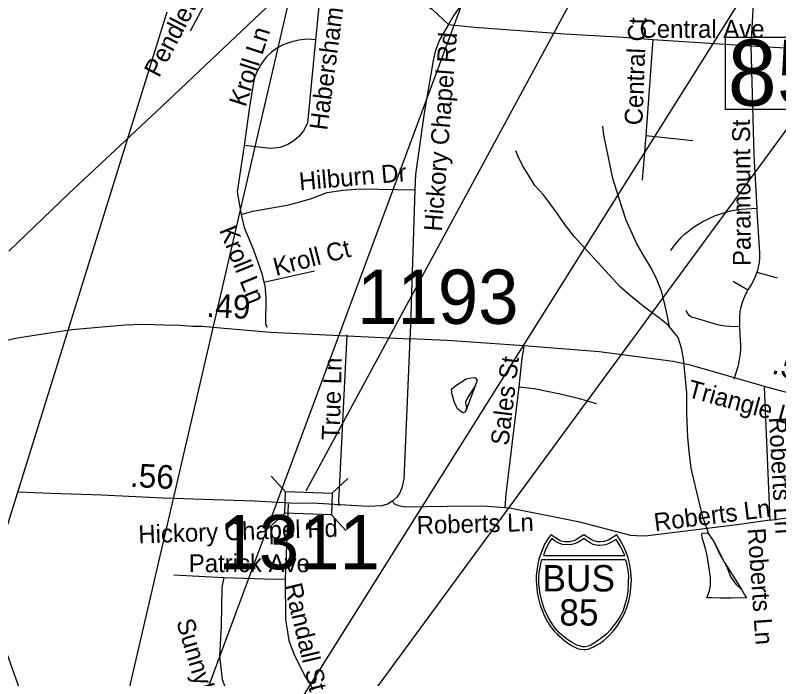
# Model space of a CAD drawing. Extents: x 1662474 to 1856135, y 779280 to 917889.
# Drawn here: x 1711717 to 1715769, y 802097 to 805619 of the extents above; entities that cross this region are included whole.
import ezdxf

# ---------------------------------------------------------------- set-up
doc = ezdxf.new("R2010")
doc.units = 0
for name, color, linetype in [('Cogo Default Point CELL', 7, 'Continuous'), ('Exist Hydrographic Misc Water Feature', 7, 'Continuous'), ('Exist Road Non-System Type 51', 7, 'Continuous'), ('Exist Road Non-System Type 51 Label', 7, 'Continuous'), ('Exist Road Primary Interstate Shield Number Label', 7, 'Continuous'), ('Exist Road Primary Interstate Structure Ovrhead Sign CELL', 7, 'Continuous'), ('Exist Road Primary US Ramp 1 Lane  Attributed', 7, 'Continuous'), ('Exist Road Secondary Mileage Tenths English Label', 7, 'Continuous'), ('Exist Road Secondary Structure Standard Bridge CELL', 7, 'Continuous'), ('Exist Road Secondary Structure Standard Bridge Number Label', 7, 'Continuous'), ('Exist Road Secondary Type 51 Attributed', 7, 'Continuous'), ('Exist Road Secondary Type 51 Label', 7, 'Continuous'), ('Exist Road Secondary Type 51 Undivided 4 Lane Attributed', 7, 'Continuous'), ('Exist Utilities Electrical Transmission Line', 7, 'Continuous'), ('Prop DGN Element Guardrail', 7, 'Continuous'), ('Prop Roadway Culvert', 7, 'Continuous'), ('Scratch_Level_2', 7, 'Continuous')]:
    doc.layers.add(name, color=color, linetype=linetype)

msp = doc.modelspace()

# ---------------------------------------------------------------- linework, layer by layer
at = {"layer": 'Exist Hydrographic Misc Water Feature'}
for points in [[(1715189.8, 803964.3), (1715176.4, 804028.4), (1715161.1, 804098.6), (1715147.6, 804154.8), (1715120.2, 804221), (1715090.7, 804279.3), (1715053.4, 804341.7), (1715015.9, 804406.1), (1714959.1, 804530.7), (1714918.2, 804657.1), (1714889.2, 804751.4), (1714852.8, 804923.8), (1714841.3, 804981.9), (1714835.7, 805030)], [(1715189.8, 803964.3), (1715181.8, 803974.4), (1715130.3, 804016.9), (1715058.7, 804067.6), (1714993.2, 804120.2), (1714929.7, 804174.8), (1714791.1, 804326.2), (1714684.2, 804445.2), (1714634.9, 804507.7), (1714591.4, 804570.1), (1714520.2, 804664.9), (1714474.7, 804715.3), (1714453, 804749.6), (1714409.7, 804822), (1714384.1, 804872.2), (1714374.3, 804898.4)], [(1715399.5, 802860), (1715366.4, 802954.3), (1715318.2, 803154.9), (1715304.8, 803215), (1715293.6, 803303.1), (1715286.2, 803377.2), (1715281.5, 803503.3), (1715282.5, 803615.3), (1715264.3, 803797.6), (1715252.7, 803851.7), (1715235.3, 803907.9), (1715189.8, 803964.3)], [(1714032.3, 803633.2), (1714056.4, 803652.9), (1714110.8, 803688.5), (1714137, 803694.2), (1714157, 803696), (1714168.9, 803681.9), (1714158.6, 803652), (1714134.2, 803612.2), (1714120, 803592.3), (1714107.7, 803564.5), (1714111.5, 803532.4), (1714107.2, 803514.4), (1714093.2, 803508.6), (1714065.3, 803528.8), (1714047.7, 803563), (1714036.1, 803605.1), (1714032.3, 803633.2)], [(1714032.3, 803633.2), (1714056.4, 803652.9), (1714110.8, 803688.5), (1714137, 803694.2), (1714157, 803696), (1714168.9, 803681.9), (1714158.6, 803652), (1714107.2, 803514.4), (1714093.2, 803508.6), (1714065.3, 803528.8), (1714047.7, 803563), (1714036.1, 803605.1), (1714032.3, 803633.2)], [(1715514.2, 802524.8), (1715460.2, 802525.3), (1715412.2, 802525.8), (1715388.2, 802526), (1715402.6, 802563.9), (1715406.9, 802593.8), (1715407.4, 802635.8), (1715399.7, 802681.9), (1715394, 802714), (1715390.4, 802752), (1715380.7, 802788.2), (1715371, 802816.2), (1715363.2, 802844.4), (1715361.5, 802862.4), (1715365.5, 802872.3), (1715391.5, 802870.1), (1715399.5, 802860)], [(1715514.2, 802524.8), (1715460.2, 802525.3), (1715412.2, 802525.8), (1715388.2, 802526), (1715402.6, 802563.9), (1715406.9, 802593.8), (1715407.4, 802635.8), (1715390.4, 802752), (1715380.7, 802788.2), (1715371, 802816.2), (1715363.2, 802844.4), (1715361.5, 802862.4), (1715365.5, 802872.3), (1715391.5, 802870.1), (1715399.5, 802860)], [(1715399.5, 802860), (1715425.1, 802825.8), (1715454.5, 802759.4), (1715482.1, 802713.2), (1715495.9, 802685), (1715515.4, 802636.8), (1715541, 802598.6), (1715572.8, 802568.3), (1715586.5, 802546.1), (1715598.4, 802526), (1715518.2, 802524.8), (1715514.2, 802524.8)], [(1715399.5, 802860), (1715425.1, 802825.8), (1715482.1, 802713.2), (1715572.8, 802568.3), (1715586.5, 802546.1), (1715598.4, 802526), (1715518.2, 802524.8), (1715514.2, 802524.8)]]:
    msp.add_lwpolyline(points, dxfattribs=at)
at = {"layer": 'Exist Road Non-System Type 51'}
for p, q in [((1715641.1, 805800.6), (1715620.9, 805456.9)), ((1715102, 805490.7), (1715063.4, 804979.7)), ((1715102, 805490.7), (1715620.9, 805456.9)), ((1715620.9, 805456.9), (1716237.8, 805419)), ((1715063.4, 804979.7), (1715045.4, 804743.2)), ((1715063.4, 804979.7), (1715313.4, 804953.4)), ((1713037.2, 804202.2), (1713305.5, 804262.4)), ((1715653.5, 804255.2), (1715761.1, 804224.2)), ((1715528.2, 804206.9), (1715606, 804160.5)), ((1715692.4, 803644.5), (1715723, 802939.2)), ((1713166.1, 803025.1), (1713150.6, 802627.8)), ((1715723, 802939.2), (1715937.8, 802967.9)), ((1712558.8, 802649), (1712824.1, 802634.9))]:
    msp.add_line(p, q, dxfattribs=at)
for points in [[(1713199.4, 806012.9), (1713249.9, 805952.6), (1713287.6, 805887.8), (1713319.4, 805794.9), (1713328.9, 805664.2), (1713311.2, 805488.6)], [(1712742.2, 805934.8), (1712726.8, 805776.2), (1712711.9, 805660.2), (1712644.9, 805534.8)], [(1714238.2, 805896.2), (1714043, 805615.1), (1714016.5, 805568.9)], [(1713632.5, 805718.2), (1713789.5, 805705.1), (1713824.1, 805700.1), (1713860.9, 805687.2), (1713885.5, 805677.2), (1713929.4, 805651.2), (1714016.5, 805568.9)], [(1714016.5, 805568.9), (1713968.8, 805489.1), (1713945.6, 805426.4), (1713934.4, 805378.4), (1713887.9, 805099.9), (1713841.9, 804775.2), (1713838.6, 804691.2)], [(1714016.5, 805568.9), (1714154.2, 805555.2), (1714634.4, 805520.9), (1714944.9, 805503.2), (1715102, 805490.7)], [(1713311.2, 805488.6), (1713266.9, 805491.2), (1713222.9, 805487.2), (1713184.5, 805478.4), (1713142.8, 805463.6), (1713108.4, 805445.2), (1713077.4, 805423.5), (1713048.2, 805395.4), (1713023.4, 805362.9), (1713000.5, 805322.7), (1712985.2, 805282.8), (1712960.4, 805132.7), (1712931.5, 804928.2)], [(1713311.2, 805488.6), (1713268.5, 805045.8), (1713247.2, 805005.4), (1713223.1, 804974.9), (1713195.5, 804951.4), (1713163.8, 804932.2), (1713123.1, 804917.4), (1713072.1, 804911.2), (1712931.5, 804928.2)], [(1715620.9, 805456.9), (1715636.9, 804876.2), (1715653.2, 804594.1)], [(1712931.5, 804928.2), (1712895.5, 804681.2), (1712916.5, 804561)], [(1712916.5, 804561), (1712977.4, 804578.1), (1713170.1, 804613), (1713284.5, 804644.2), (1713372.1, 804677.2), (1713455.9, 804690.9), (1713547.5, 804698.2), (1713838.6, 804691.2)], [(1713838.6, 804691.2), (1713813.4, 803925.6), (1713809.4, 803889.1)], [(1715196, 804370.8), (1715212.2, 804393), (1715251.4, 804439), (1715269.5, 804456.2), (1715289.6, 804472.9), (1715303.4, 804483.6), (1715317.8, 804493.9), (1715339.9, 804508), (1715362.6, 804521.4), (1715400.1, 804540.6), (1715417, 804548.4), (1715434.6, 804555.5), (1715461.4, 804565.2), (1715488.4, 804573.4), (1715515.9, 804580.7), (1715543.5, 804585.4), (1715571.9, 804589.6), (1715599.9, 804591.8), (1715653.2, 804594.1)], [(1715653.2, 804594.1), (1715654, 804579.4), (1715667.1, 804357.1), (1715667.1, 804331.9), (1715665, 804304.6), (1715660.9, 804282.9), (1715657.6, 804269.7), (1715653.5, 804255.2)], [(1712916.5, 804561), (1712932.5, 804492.5), (1712981.4, 804373.6), (1713026, 804247.7), (1713037.2, 804202.2)], [(1715653.5, 804255.2), (1715646.6, 804236.1), (1715635.9, 804211.2), (1715625.6, 804191.8), (1715606, 804160.5)], [(1713037.2, 804202.2), (1713042, 804183.6), (1713047.5, 804123), (1713045.4, 803979.9), (1713054.9, 803962.6)], [(1715606, 804160.5), (1715600.1, 804151.1), (1715595.1, 804141.6), (1715584.1, 804117.2), (1715575.2, 804093.6), (1715568.4, 804068.9), (1715563.8, 804044.8), (1715561.1, 804019.6), (1715560.6, 804009.1), (1715561.6, 803968.9)], [(1715276.6, 804053.2), (1715280, 804044.5), (1715285, 804036.4), (1715291.2, 804029), (1715298.6, 804022.7), (1715306.2, 804018), (1715315.1, 804014.6), (1715326.4, 804012.8), (1715437.5, 803979.7), (1715461.4, 803973.9), (1715486, 803969.7), (1715510.9, 803967.6), (1715535.9, 803967.4), (1715561.6, 803968.9)], [(1715561.6, 803968.9), (1715563.1, 803918.2), (1715565.2, 803893.9), (1715566.4, 803870.2), (1715565.9, 803846.9), (1715564.2, 803823.2), (1715559.8, 803792), (1715554, 803761.4), (1715552.1, 803753.4), (1715531.9, 803687.9)], [(1713477.6, 803922.2), (1713437, 803105.4), (1713432, 803045.4), (1713433.9, 803015.4)], [(1714416.5, 803858.9), (1714406.5, 803799.4), (1714389.1, 803646.6)], [(1714389.1, 803646.6), (1714320.4, 803076), (1714315.4, 803003.4)], [(1714389.1, 803646.6), (1714471.6, 803636.9), (1714618.1, 803607.5), (1714704.4, 803586.8), (1714800.5, 803558.7)], [(1714315.4, 803003.4), (1714222.8, 803011.4), (1714120.6, 803012.5), (1713786.9, 803008), (1713750.9, 803013.9), (1713731.8, 803023.8), (1713716.2, 803041.9)], [(1715723, 802939.2), (1715560.9, 802916.2), (1715060.9, 802853.4), (1715014.1, 802854.8), (1714983.6, 802856.9), (1714714.6, 802927.2), (1714340.4, 803001.5), (1714315.4, 803003.4)], [(1712824.1, 802634.9), (1712813.9, 802583.4), (1712809.9, 802375.5), (1712801.9, 802216.2), (1712815.8, 802092.6), (1712856.1, 801985.5), (1712896.9, 801906.8), (1712921, 801866.1), (1712937.2, 801845.4)], [(1712824.1, 802634.9), (1713094.8, 802625.9), (1713150.6, 802627.8)], [(1713150.6, 802627.8), (1713151.1, 802411.8), (1713169.2, 802300.4), (1713197.4, 802223.8), (1713258.2, 802104.7), (1713286.6, 802062.4), (1713296.9, 802038)]]:
    msp.add_lwpolyline(points, dxfattribs=at)
at = {"layer": 'Exist Road Primary Interstate Structure Ovrhead Sign CELL'}
msp.add_line((1712430.6, 801213.7), (1714482.1, 806737.8), dxfattribs=at)
at = {"layer": 'Exist Road Primary US Ramp 1 Lane  Attributed'}
msp.add_lwpolyline([(1711531.9, 802624.8), (1711583, 802474.9), (1711672.1, 802231.7), (1711794.1, 801887.9), (1711897.7, 801605.3), (1711971.2, 801402.4), (1712043.2, 801239.1), (1712165.6, 801028.7), (1712215.6, 800953.8)], dxfattribs=at)
at = {"layer": 'Exist Road Secondary Structure Standard Bridge CELL'}
for p, q in [((1713151.6, 803089.6), (1713074.6, 803172.5)), ((1713482.3, 803159.5), (1713399.4, 803082.5)), ((1713147.4, 802976.5), (1713064.5, 802899.4)), ((1713472.1, 802883.8), (1713395.1, 802966.7))]:
    msp.add_line(p, q, dxfattribs=at)
msp.add_lwpolyline([(1713395.1, 802966.7), (1713147.4, 802975.9), (1713151.7, 803091.6), (1713399.4, 803082.5)], close=True, dxfattribs=at)
at = {"layer": 'Exist Road Secondary Structure Standard Bridge Number Label'}
msp.add_line((1713261.4, 803095.2), (1715012.8, 806331.1), dxfattribs=at)
at = {"layer": 'Exist Road Secondary Type 51 Attributed'}
for points in [[(1713810.8, 803901.7), (1713778.9, 803156.9), (1713769.1, 803109.6), (1713757.8, 803083.9), (1713744.5, 803063.4), (1713721.8, 803041.8), (1713693, 803023.3), (1713662.7, 803015), (1713589.7, 803011.9), (1713293.7, 803029.7)], [(1716803.4, 803346.2), (1716711.2, 803370.6), (1716381.1, 803454.1), (1716040.6, 803554), (1715693.9, 803647.7), (1715300.5, 803761), (1715208.4, 803781.4), (1714816.2, 803832.5), (1714417.1, 803863.7), (1714009.1, 803893.1), (1713810.8, 803901.7)], [(1713293.7, 803029.7), (1713249, 803027.7), (1713176, 803028.9), (1712984.8, 803039.3), (1712501.5, 803056.2), (1712174.6, 803071.6), (1711906.7, 803079.8), (1711733, 803088)]]:
    msp.add_lwpolyline(points, dxfattribs=at)
at = {"layer": 'Exist Road Secondary Type 51 Undivided 4 Lane Attributed'}
msp.add_lwpolyline([(1711565.4, 803870.9), (1711719.9, 803903.9), (1711806.1, 803919), (1712017.4, 803951.3), (1712198.4, 803966.4), (1712302.4, 803975.2), (1712392.2, 803978.5), (1712457.1, 803977.2), (1712505.7, 803975.8), (1712588.9, 803973.7), (1712659.7, 803968.6), (1712709.3, 803968.6), (1712825.7, 803957.8), (1713072.4, 803936.3), (1713810.8, 803901.7)], dxfattribs=at)
at = {"layer": 'Exist Utilities Electrical Transmission Line'}
msp.add_lwpolyline([(1711682.4, 804367.2), (1712000.4, 804670.6), (1712495, 805135.2), (1713050.2, 805659.3), (1713449.3, 806029.3), (1713779.5, 806348.5), (1714124.4, 806683.5), (1714460.6, 806996.7), (1714551.9, 807077.2), (1714763.8, 807525.9), (1714928.9, 807877.4), (1715065, 808165.4), (1715330.2, 808405.6), (1715755.5, 808789.2)], dxfattribs=at)
at = {"layer": 'Prop Roadway Culvert'}
for points in [[(1714734.9, 802251.4), (1714744.4, 802252.3), (1714757.1, 802254.8), (1714769.5, 802258.9), (1714783.6, 802265.1), (1714804.4, 802276.7), (1714821.2, 802286.5), (1714840.5, 802299.5), (1714866.6, 802323.2), (1714892.7, 802350.6), (1714915.7, 802381.7), (1714933.9, 802410.7), (1714950, 802443.8), (1714963.4, 802474.7), (1714974.1, 802510.1), (1714981.2, 802544.3), (1714984.7, 802580), (1714987.1, 802619.6), (1714984.4, 802664.1), (1714976.7, 802709.7), (1714969.4, 802738), (1714958.4, 802772), (1714949.4, 802793.6), (1714928.5, 802832.1), (1714909.8, 802861.7), (1714882.6, 802842.5), (1714864.8, 802833.1), (1714854, 802828.2), (1714842.8, 802826), (1714822.3, 802823.5), (1714809.4, 802824.1), (1714797.5, 802826.8), (1714787.4, 802829), (1714779.1, 802833.1), (1714734.9, 802861.7), (1714690.6, 802833.1), (1714681.3, 802828.8), (1714671.8, 802826.8), (1714662.7, 802824.3), (1714647.5, 802823.5), (1714636, 802823.9), (1714624.1, 802826), (1714614.7, 802828), (1714604.2, 802833.1), (1714559.1, 802861.7), (1714541.4, 802836), (1714526.9, 802810.5), (1714511.5, 802774.6), (1714502, 802746.8), (1714495.2, 802723.9), (1714486.8, 802682), (1714482.5, 802645.4), (1714481.8, 802619.6), (1714486.5, 802555), (1714493.5, 802520.7), (1714500.8, 802492.9), (1714524.6, 802432.9), (1714542.6, 802399.2), (1714558, 802375.1), (1714579.6, 802347.9), (1714591.3, 802335), (1714636.1, 802295.8), (1714666, 802275.3), (1714689.9, 802262.4), (1714701.1, 802258.2), (1714718.7, 802253.3)], [(1714564.5, 802840.9), (1714553.5, 802824), (1714540.8, 802801.2), (1714530.6, 802777.5), (1714520.3, 802751.3), (1714951.8, 802751.2), (1714941.8, 802773.6), (1714931, 802796.1), (1714919.8, 802816.7), (1714906.1, 802836.6), (1714881.9, 802821.3), (1714864.3, 802813), (1714850.1, 802808.1), (1714838.1, 802805.4), (1714819.5, 802804), (1714811.2, 802804.4), (1714785.2, 802810.3), (1714767.7, 802817.5), (1714751, 802828.6), (1714737.5, 802841.4), (1714703.3, 802820.7), (1714688.1, 802814), (1714670.7, 802809.5), (1714651.6, 802807.1), (1714622.1, 802810.3), (1714599.1, 802818.3), (1714579.2, 802828.6)], [(1714954.4, 802729.9), (1714959, 802717.7), (1714965.4, 802690.6), (1714968.7, 802669.8), (1714972.1, 802645.8), (1714970.9, 802604.7), (1714969, 802562.1), (1714965, 802536.9), (1714959.8, 802514), (1714952.7, 802488.5), (1714941.1, 802454.7), (1714925.2, 802426), (1714905.3, 802394.2), (1714883.9, 802366.3), (1714874.5, 802354.8), (1714856.8, 802336.1), (1714824.6, 802310.2), (1714801.1, 802292.6), (1714772.9, 802276), (1714758.6, 802269.6), (1714741.9, 802266.1), (1714728.2, 802267.1), (1714711.6, 802271.5), (1714698.1, 802275.2), (1714668.7, 802291.1), (1714644.9, 802307), (1714605.1, 802339.7), (1714583.6, 802364.8), (1714563.6, 802394.2), (1714545.7, 802424.3), (1714526.6, 802463.9), (1714513.2, 802503.8), (1714503.4, 802546.9), (1714496.8, 802599.6), (1714496.1, 802631.6), (1714498, 802662.5), (1714501, 802678.6), (1714504.9, 802698.7), (1714512.7, 802729.7)]]:
    msp.add_lwpolyline(points, close=True, dxfattribs=at)
at = {"layer": 'Scratch_Level_2'}
for p, q in [((1712463.9, 800761), (1716241.1, 806773)), ((1712068.6, 800946.6), (1713292.3, 806225.4)), ((1711617.2, 802724.1), (1712522.7, 805636.8)), ((1712420.6, 800394.1), (1715864.4, 805083.3))]:
    msp.add_line(p, q, dxfattribs=at)
msp.add_lwpolyline([(1715486, 805503.2), (1716415, 805503.2), (1716415, 805119.1), (1715486, 805119.1)], close=True, dxfattribs=at)

# ---------------------------------------------------------------- texts
at = {"layer": 'Cogo Default Point CELL'}
for s, p in [('1193', (1713531.6, 803980.7)), ('1311', (1712795.5, 802678))]:
    msp.add_text(s, height=288, dxfattribs=at).set_placement(p)
at = {"layer": 'Exist Road Non-System Type 51 Label'}
for s, rotation, p in [('Pendleton St', 62.3325, (1712480.3, 805283.4)), ('Habersham Rd', 82.4128, (1713372.2, 805004.8)), ('Central Ct', 87.8223, (1715045.5, 805033.5)), ('Kroll Ln', 72.1584, (1712939.5, 805127.6)), ('Hickory Chapel Rd', 85.5937, (1713980.9, 804468.8)), ('Paramount St', 90.3271, (1715621.1, 804287.9)), ('Hilburn Dr', 4.9802, (1713227.2, 804689.2)), ('Kroll Ln', 291.9628, (1712798.3, 804478.6)), ('Kroll Ct', 14.4287, (1713100.6, 804234.6)), ('True Ln', 88.3631, (1713438.3, 803362.7)), ('Sales St', 83.1467, (1714334.4, 803331.8)), ('Roberts Ln', 273.2819, (1715716.1, 803483.7)), ('Roberts Ln', 7.1666, (1715113.2, 802879.7)), ('Roberts Ln', 1.5088, (1713848.9, 802864.8)), ('Roberts Ln', 273.9886, (1715603.8, 802894)), ('Randall St', 283.5283, (1713144, 802592.5)), ('Sunnybrook St', 286.6734, (1712571, 802400.4))]:
    msp.add_text(s, height=95, rotation=rotation, dxfattribs=at).set_placement(p)
for s, p in [('Central Ave', (1715030.5, 805498.9)), ('Patrick Ave', (1712638.3, 802662.7))]:
    msp.add_text(s, height=95, dxfattribs=at).set_placement(p)
at = {"layer": 'Exist Road Primary Interstate Shield Number Label'}
for s, p in [('BUS', (1714515.5, 802560.4)), ('85', (1714604.8, 802379.1))]:
    msp.add_text(s, height=140, dxfattribs=at).set_placement(p)
at = {"layer": 'Exist Road Secondary Mileage Tenths English Label'}
msp.add_text('.55', height=125, rotation=343.9372, dxfattribs=at).set_placement((1715726.6, 803719.3))
at = {"layer": 'Exist Road Secondary Type 51 Label'}
for s, rotation, p in [('Triangle Lake Rd', 344.763, (1715279.2, 803593.7)), ('Hickory Chapel Rd', 1.9025, (1712372, 802815.6))]:
    msp.add_text(s, height=95, rotation=rotation, dxfattribs=at).set_placement(p)
at = {"layer": 'Prop DGN Element Guardrail'}
for s, rotation, p in [('.49', 357.3217, (1712730, 804017.6)), ('.56', 357.0283, (1712323.9, 803115.9))]:
    msp.add_text(s, height=125, rotation=rotation, dxfattribs=at).set_placement(p)
at = {"layer": 'Scratch_Level_2'}
msp.add_text('857', height=350, dxfattribs=at).set_placement((1715498.5, 805138.9))

doc.saveas('drawing.dxf')
